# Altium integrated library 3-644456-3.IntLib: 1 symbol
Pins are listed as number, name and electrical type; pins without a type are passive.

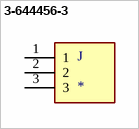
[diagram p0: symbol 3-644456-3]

## 3-644456-3
designator J
MTA-100 3 Position Through-Hole Single Row Straight Wire to Board Header; MP: 3-644456-3; Centerline_Pitch: 2.54 mm[.1 in]; Product_Type: Connector; MF: TE Connectivity; Number_of_Positions: 3
footprint TE_3-644456-3
pins: 1, 2, 3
